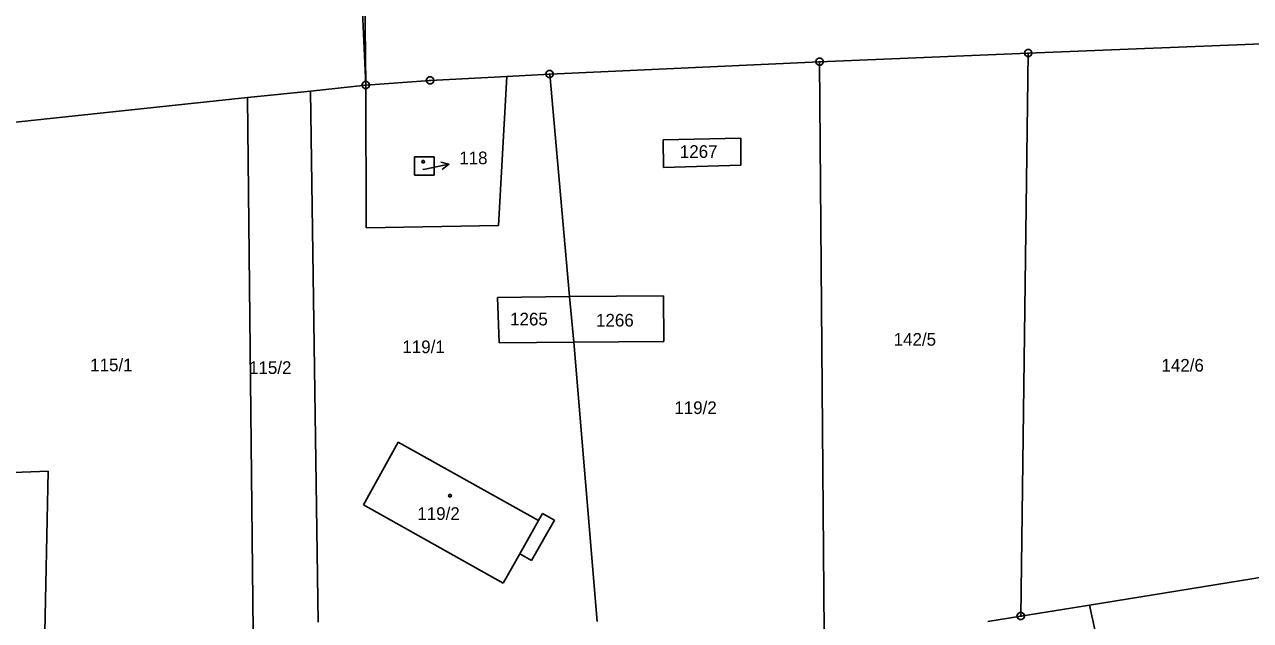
# Model space of a CAD drawing. Extents: x -812394 to -807601, y -1013098 to -1009266.
# Drawn here: x -809776.7 to -809612.2, y -1010672.7 to -1010592.7 of the extents above; entities that cross this region are included whole.
import ezdxf

# ---------------------------------------------------------------- set-up
doc = ezdxf.new("R2010")
doc.units = 0
for name, color, linetype in [('KN_HRANICE', 7, 'Continuous'), ('KN_KULTURY', 7, 'Continuous'), ('KN_MEZNIKY', 7, 'Continuous'), ('KN_PARCELY', 7, 'Continuous'), ('KN_SLUCKY', 7, 'Continuous')]:
    doc.layers.add(name, color=color, linetype=linetype)

# ---------------------------------------------------------------- blocks, each defined once
blk = doc.blocks.new('10292')
blk.add_line((0, 3), (0, 0))
blk.add_lwpolyline([(-0.5, 2), (0, 3), (0.5, 2)])
blk = doc.blocks.new('105')
blk.add_line((-0.12, 0), (0.12, 0))
blk.add_lwpolyline([(0.15, 0.48), (0.4, 0.3), (0.5, 0.01), (0.4, -0.28), (0.15, -0.46), (-0.16, -0.46), (-0.41, -0.28), (-0.51, 0.01), (-0.41, 0.3), (-0.16, 0.48), (0.15, 0.48)])
blk = doc.blocks.new('402')
blk.add_lwpolyline([(0.09, 0.15), (0.18, 0), (0.09, -0.15), (-0.09, -0.15), (-0.18, 0), (-0.09, 0.15), (0.09, 0.15)])

msp = doc.modelspace()

# ---------------------------------------------------------------- linework, layer by layer
at = {"layer": 'KN_HRANICE'}
for p, q in [((-809730.9, -1010600.87), (-809735.22, -1010505.35)), ((-809730.9, -1010600.87), (-809731.22, -1010570.09)), ((-809594.54, -1010594.65), (-809642.04, -1010596.56)), ((-809642.04, -1010596.56), (-809670.02, -1010597.72)), ((-809642.04, -1010596.56), (-809643.04, -1010672.11)), ((-809670.02, -1010597.72), (-809706.23, -1010599.39)), ((-809669.42, -1010674.32), (-809670.02, -1010597.72)), ((-809722.27, -1010600.23), (-809730.9, -1010600.87)), ((-809722.27, -1010600.23), (-809711.97, -1010599.69)), ((-809711.97, -1010599.69), (-809713.11, -1010619.7)), ((-809711.97, -1010599.69), (-809706.23, -1010599.39)), ((-809703.55, -1010629.24), (-809706.23, -1010599.39)), ((-809746.74, -1010602.54), (-809738.29, -1010601.65)), ((-809738.29, -1010601.65), (-809730.9, -1010600.87)), ((-809738.29, -1010601.65), (-809737.29, -1010672.93)), ((-809730.84, -1010620.01), (-809730.9, -1010600.87)), ((-809785.03, -1010606.6), (-809746.74, -1010602.54)), ((-809745.99, -1010674.27), (-809746.74, -1010602.54)), ((-809691.02, -1010608.19), (-809680.61, -1010607.97)), ((-809690.96, -1010611.9), (-809691.02, -1010608.19)), ((-809680.61, -1010607.97), (-809680.61, -1010611.61)), ((-809680.61, -1010611.61), (-809690.96, -1010611.9)), ((-809713.11, -1010619.7), (-809730.84, -1010620.01)), ((-809713.23, -1010629.34), (-809703.55, -1010629.24)), ((-809713.01, -1010635.43), (-809713.23, -1010629.34)), ((-809703.55, -1010629.24), (-809690.96, -1010629.11)), ((-809703, -1010635.36), (-809703.55, -1010629.24)), ((-809690.96, -1010629.11), (-809690.9, -1010635.27)), ((-809703, -1010635.36), (-809713.01, -1010635.43)), ((-809690.9, -1010635.27), (-809703, -1010635.36)), ((-809699.85, -1010672.81), (-809703, -1010635.36)), ((-809731.21, -1010657.15), (-809726.56, -1010648.77)), ((-809726.56, -1010648.77), (-809707.72, -1010659.29)), ((-809773.49, -1010652.65), (-809779.36, -1010652.87)), ((-809774.04, -1010679.33), (-809773.49, -1010652.65)), ((-809712.47, -1010667.68), (-809731.21, -1010657.15)), ((-809705.6, -1010659.22), (-809708.67, -1010664.64)), ((-809707.72, -1010659.29), (-809707.18, -1010658.33)), ((-809707.18, -1010658.33), (-809705.6, -1010659.22)), ((-809710.24, -1010663.75), (-809712.47, -1010667.68)), ((-809708.67, -1010664.64), (-809710.24, -1010663.75)), ((-809633.83, -1010670.62), (-809598.46, -1010664.88)), ((-809643.04, -1010672.11), (-809633.83, -1010670.62)), ((-809632.78, -1010675.32), (-809633.83, -1010670.62)), ((-809647.44, -1010672.82), (-809643.04, -1010672.11))]:
    msp.add_line(p, q, dxfattribs=at)
at = {"layer": 'KN_PARCELY'}
msp.add_line((-809723.21, -1010612.18), (-809722.69, -1010612.07), dxfattribs=at)
at = {"layer": 'KN_SLUCKY'}
for p, q in [((-809724.37, -1010612.96), (-809724.37, -1010610.49)), ((-809721.71, -1010610.49), (-809724.37, -1010610.49)), ((-809721.71, -1010612.96), (-809721.71, -1010610.49)), ((-809724.37, -1010612.96), (-809721.71, -1010612.96)), ((-809710.24, -1010663.75), (-809707.72, -1010659.29))]:
    msp.add_line(p, q, dxfattribs=at)

# ---------------------------------------------------------------- block references
at = {"layer": 'KN_KULTURY'}
for p in [(-809723.19, -1010611.14), (-809719.6, -1010655.95)]:
    msp.add_blockref('402', p, dxfattribs=at)
at = {"layer": 'KN_MEZNIKY'}
for p in [(-809670.02, -1010597.72), (-809642.04, -1010596.56), (-809730.9, -1010600.87), (-809722.27, -1010600.23), (-809706.23, -1010599.39), (-809643.04, -1010672.11)]:
    msp.add_blockref('105', p, dxfattribs=at)
at = {"layer": 'KN_PARCELY', "rotation": -78.391244}
msp.add_blockref('10292', (-809722.69, -1010612.07), dxfattribs=at)

# ---------------------------------------------------------------- texts
at = {"layer": 'KN_PARCELY'}
for s, height, p in [('118', 1.7, (-809718.36, -1010611.47)), ('1267', 1.7, (-809688.77, -1010610.62)), ('118', 0.1, (-809723.36, -1010612.18)), ('1265', 1.7, (-809711.54, -1010633.1)), ('1266', 1.7, (-809700.01, -1010633.25)), ('119/1', 1.7, (-809725.99, -1010636.82)), ('142/5', 1.7, (-809660.09, -1010635.82)), ('115/1', 1.7, (-809767.86, -1010639.25)), ('115/2', 1.7, (-809746.56, -1010639.61)), ('142/6', 1.7, (-809624.17, -1010639.3)), ('119/2', 1.7, (-809689.51, -1010644.99)), ('119/2', 1.7, (-809723.98, -1010659.2))]:
    msp.add_text(s, height=height, dxfattribs=at).set_placement(p)

doc.saveas('drawing.dxf')
